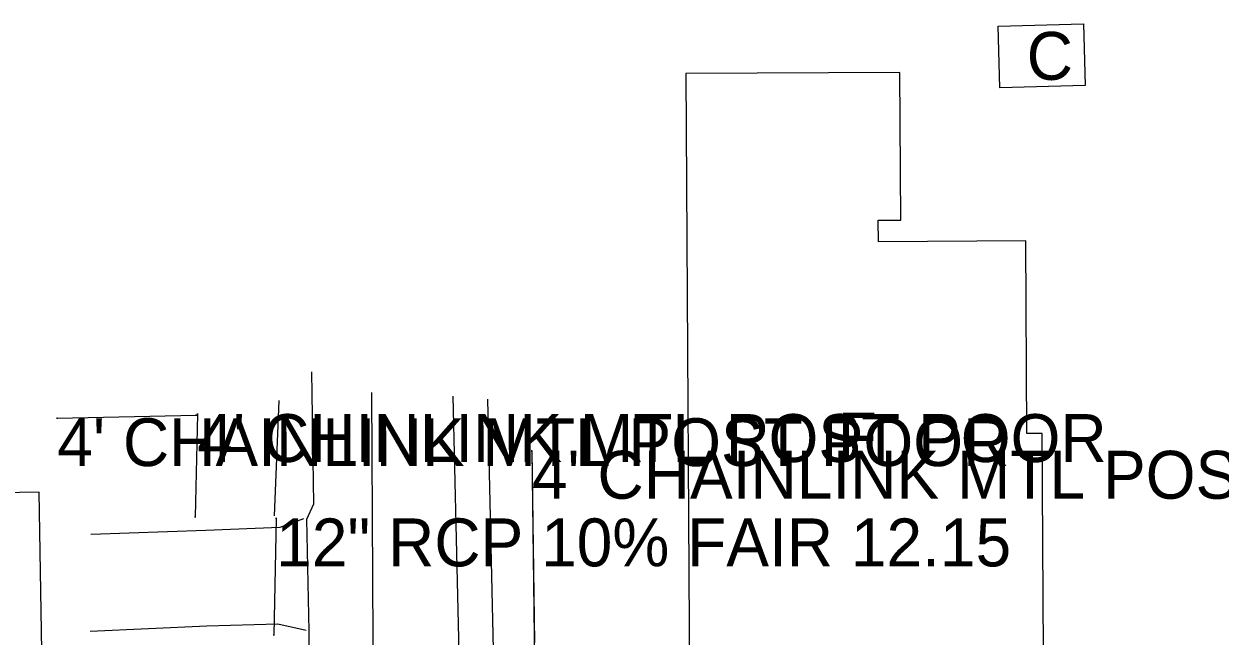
# Model space of a CAD drawing. Extents: x 1304270 to 1306561, y 1876019 to 1876752.
# Drawn here: x 1305299.9 to 1305424.7, y 1876482.3 to 1876546.1 of the extents above; entities that cross this region are included whole.
import ezdxf

# ---------------------------------------------------------------- set-up
doc = ezdxf.new("R2010")
doc.units = 0
for name, color, linetype in [('S_BUILDING', 7, 'Continuous'), ('S_BUILDING_ANNOT', 7, 'Continuous'), ('S_DITCHLINE', 7, 'Continuous'), ('S_DRG_PT_SYM', 7, 'Continuous'), ('S_DRIVEWAY', 7, 'Continuous'), ('S_EDGE_PAVEMENT', 7, 'Continuous'), ('S_FENCE', 7, 'Continuous'), ('S_FENCE_ANNOT', 7, 'Continuous'), ('S_MSC_PT_SYM', 7, 'Continuous'), ('S_PAVEMENT_CROWN', 7, 'Continuous'), ('S_SIDE_DRAIN', 7, 'Continuous'), ('S_SIDE_DRAIN_ANNOT', 7, 'Continuous')]:
    doc.layers.add(name, color=color, linetype=linetype)

msp = doc.modelspace()

# ---------------------------------------------------------------- linework, layer by layer
at = {"layer": 'S_BUILDING'}
for points in [[(1305401.56, 1876545.91), (1305410.47, 1876546.15), (1305410.65, 1876539.71), (1305401.73, 1876539.47)], [(1305368.98, 1876540.96), (1305369.42, 1876465.83), (1305390.64, 1876465.95), (1305390.62, 1876469.14), (1305406.36, 1876469.24), (1305406.16, 1876503.4), (1305404.58, 1876503.39), (1305404.46, 1876523.5), (1305389.08, 1876523.41), (1305389.06, 1876525.65), (1305391.41, 1876525.66), (1305391.32, 1876541.09)], [(1305281, 1876496.94), (1305281.8, 1876448.54), (1305301.42, 1876448.87), (1305301.27, 1876457.78), (1305308.02, 1876457.89), (1305307.85, 1876468.4), (1305301.98, 1876468.31), (1305301.5, 1876497.28)]]:
    msp.add_lwpolyline(points, close=True, dxfattribs=at)
at = {"layer": 'S_DITCHLINE'}
for points in [[(1305348.27, 1876506.97), (1305348.62, 1876491.61), (1305348.97, 1876476.25), (1305349.4, 1876455.77), (1305349.84, 1876435.29), (1305350.39, 1876429.75), (1305350.93, 1876425.39)], [(1305326.51, 1876506.85), (1305326, 1876494.82)]]:
    msp.add_lwpolyline(points, dxfattribs=at)
at = {"layer": 'S_DRG_PT_SYM'}
for points in [[(1305326.23, 1876494.53), (1305326.23, 1876494.58), (1305326.23, 1876494.53), (1305326.18, 1876494.53), (1305326.23, 1876494.53), (1305326.23, 1876494.48), (1305326.23, 1876494.53), (1305326.28, 1876494.53)], [(1305325.99, 1876482.38), (1305325.99, 1876482.43), (1305325.99, 1876482.38), (1305325.94, 1876482.38), (1305325.99, 1876482.38), (1305325.99, 1876482.33), (1305325.99, 1876482.38), (1305326.04, 1876482.38)]]:
    msp.add_lwpolyline(points, dxfattribs=at)
at = {"layer": 'S_DRIVEWAY'}
for points in [[(1305329.09, 1876494.48), (1305326.6, 1876493.57), (1305318.87, 1876493.28), (1305306.89, 1876492.84)], [(1305306.83, 1876482.77), (1305318.99, 1876483.33), (1305326.4, 1876483.52), (1305329.37, 1876482.86)]]:
    msp.add_lwpolyline(points, dxfattribs=at)
at = {"layer": 'S_EDGE_PAVEMENT'}
for points in [[(1305329.46, 1876463.89), (1305329.02, 1876467.77), (1305329.75, 1876473.39), (1305329.68, 1876482.77), (1305329.43, 1876494.44), (1305330.17, 1876496.06), (1305329.94, 1876509.82)], [(1305345.54, 1876422.73), (1305345.86, 1876430.1), (1305345.86, 1876438.58), (1305345.53, 1876451.96), (1305345.19, 1876465.34), (1305345.39, 1876477.54), (1305345.05, 1876492.41), (1305344.71, 1876507.28)]]:
    msp.add_lwpolyline(points, dxfattribs=at)
at = {"layer": 'S_FENCE'}
for p, q in [((1305303.38, 1876504.99), (1305317.86, 1876505.3)), ((1305318, 1876505.42), (1305317.78, 1876494.69)), ((1305352.9, 1876501.59), (1305353.24, 1876476.06))]:
    msp.add_line(p, q, dxfattribs=at)
for points in [[(1305303.38, 1876504.99), (1305317.86, 1876505.3)], [(1305303.38, 1876504.99), (1305317.86, 1876505.3)], [(1305318, 1876505.42), (1305317.78, 1876494.69)], [(1305318, 1876505.42), (1305317.78, 1876494.69)], [(1305352.9, 1876501.59), (1305353.17, 1876481.59)], [(1305352.9, 1876501.59), (1305353.17, 1876481.59)]]:
    msp.add_lwpolyline(points, dxfattribs=at)
at = {"layer": 'S_MSC_PT_SYM'}
for points in [[(1305303.38, 1876504.99), (1305303.38, 1876505.04), (1305303.38, 1876504.99), (1305303.33, 1876504.99), (1305303.38, 1876504.99), (1305303.38, 1876504.94), (1305303.38, 1876504.99), (1305303.43, 1876504.99)], [(1305317.86, 1876505.3), (1305317.86, 1876505.35), (1305317.86, 1876505.3), (1305317.81, 1876505.3), (1305317.86, 1876505.3), (1305317.86, 1876505.25), (1305317.86, 1876505.3), (1305317.91, 1876505.3)], [(1305318, 1876505.42), (1305318, 1876505.47), (1305318, 1876505.42), (1305317.95, 1876505.42), (1305318, 1876505.42), (1305318, 1876505.37), (1305318, 1876505.42), (1305318.05, 1876505.42)], [(1305352.9, 1876501.59), (1305352.9, 1876501.64), (1305352.9, 1876501.59), (1305352.85, 1876501.59), (1305352.9, 1876501.59), (1305352.9, 1876501.54), (1305352.9, 1876501.59), (1305352.95, 1876501.59)], [(1305317.78, 1876494.69), (1305317.78, 1876494.74), (1305317.78, 1876494.69), (1305317.73, 1876494.69), (1305317.78, 1876494.69), (1305317.78, 1876494.64), (1305317.78, 1876494.69), (1305317.83, 1876494.69)]]:
    msp.add_lwpolyline(points, dxfattribs=at)
at = {"layer": 'S_PAVEMENT_CROWN'}
msp.add_lwpolyline([(1305336.4, 1876469), (1305336.31, 1876488.34), (1305336.21, 1876507.68)], dxfattribs=at)
at = {"layer": 'S_SIDE_DRAIN'}
msp.add_line((1305326.23, 1876494.53), (1305325.99, 1876482.38), dxfattribs=at)

# ---------------------------------------------------------------- texts
at = {"layer": 'S_BUILDING_ANNOT'}
for s, p in [('C', (1305404.55, 1876540.31)), ('F', (1305384.82, 1876500.58))]:
    msp.add_text(s, height=5, dxfattribs=at).set_placement(p)
at = {"layer": 'S_FENCE_ANNOT'}
for s, p in [("4' CHAINLINK MTL POST POOR", (1305303.38, 1876499.99)), ("4' CHINLINK MTL POST POOR", (1305318, 1876500.42)), ("4' CHAINLINK MTL POST FAIR", (1305352.9, 1876496.59))]:
    msp.add_text(s, height=5, dxfattribs=at).set_placement(p)
at = {"layer": 'S_SIDE_DRAIN_ANNOT'}
msp.add_text('12" RCP 10% FAIR 12.15', height=5, dxfattribs=at).set_placement((1305326.23, 1876489.53))

doc.saveas('drawing.dxf')
